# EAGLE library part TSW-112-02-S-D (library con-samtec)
THROUGH-HOLE .025" SQ POST HEADER Source: Samtec TSW.pdf
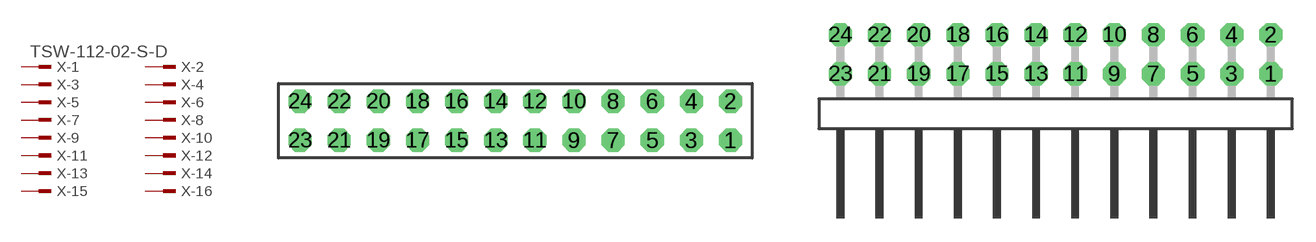
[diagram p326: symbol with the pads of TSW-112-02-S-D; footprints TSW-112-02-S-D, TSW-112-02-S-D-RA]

Designator prefix X; gates -1=MPINV -2=MPIN -3=MPIN -4=MPIN -5=MPIN -6=MPIN -7=MPIN -8=MPIN -9=MPIN -10=MPIN -11=MPIN -12=MPIN -13=MPIN -14=MPIN -15=MPIN -16=MPIN -17=MPIN -18=MPIN -19=MPIN -20=MPIN -21=MPIN -22=MPIN -23=MPIN -24=MPIN

## TSW-112-02-S-D (OC_FARNELL: unknown; OC_NEWARK: unknown)  [TSW-112-02-S-D]
1  -1:1  pas
2  -2:1  pas
3  -3:1  pas
4  -4:1  pas
5  -5:1  pas
6  -6:1  pas
7  -7:1  pas
8  -8:1  pas
9  -9:1  pas
10  -10:1  pas
11  -11:1  pas
12  -12:1  pas
13  -13:1  pas
14  -14:1  pas
15  -15:1  pas
16  -16:1  pas
17  -17:1  pas
18  -18:1  pas
19  -19:1  pas
20  -20:1  pas
21  -21:1  pas
22  -22:1  pas
23  -23:1  pas
24  -24:1  pas

## TSW-112-02-S-D-RA (OC_FARNELL: unknown; OC_NEWARK: unknown)  [TSW-112-02-S-D-RA]
Pads as for TSW-112-02-S-D

## Footprint TSW-112-02-S-D (pad centres in mm)
THROUGH-HOLE .025" SQ POST HEADER Source: Samtec TSW.pdf
drill 1 pad 1.5 octagon: 1 13.97,-1.27; 2 13.97,1.27; 3 11.43,-1.27; 4 11.43,1.27; 5 8.89,-1.27; 6 8.89,1.27; 7 6.35,-1.27; 8 6.35,1.27; 9 3.81,-1.27; 10 3.81,1.27; 11 1.27,-1.27; 12 1.27,1.27; 13 -1.27,-1.27; 14 -1.27,1.27; 15 -3.81,-1.27; 16 -3.81,1.27; 17 -6.35,-1.27; 18 -6.35,1.27; 19 -8.89,-1.27; 20 -8.89,1.27; 21 -11.43,-1.27; 22 -11.43,1.27; 23 -13.97,-1.27; 24 -13.97,1.27

## Footprint TSW-112-02-S-D-RA (pad centres in mm)
THROUGH-HOLE .025" SQ POST HEADER Source: Samtec TSW.pdf
drill 1 pad 1.5 octagon: 1 13.97,1.524; 2 13.97,4.064; 3 11.43,1.524; 4 11.43,4.064; 5 8.89,1.524; 6 8.89,4.064; 7 6.35,1.524; 8 6.35,4.064; 9 3.81,1.524; 10 3.81,4.064; 11 1.27,1.524; 12 1.27,4.064; 13 -1.27,1.524; 14 -1.27,4.064; 15 -3.81,1.524; 16 -3.81,4.064; 17 -6.35,1.524; 18 -6.35,4.064; 19 -8.89,1.524; 20 -8.89,4.064; 21 -11.43,1.524; 22 -11.43,4.064; 23 -13.97,1.524; 24 -13.97,4.064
